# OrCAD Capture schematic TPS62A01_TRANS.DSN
size D; title: TPS62A01, 1-A High-Efficiency Synchronous; rev: 1.0; note: Datasheet: SLUSEG9B          EVM:SLUUCJ1; note: Synchronous Step Down Converter; note: Buck Converters in a SOT-563 Package
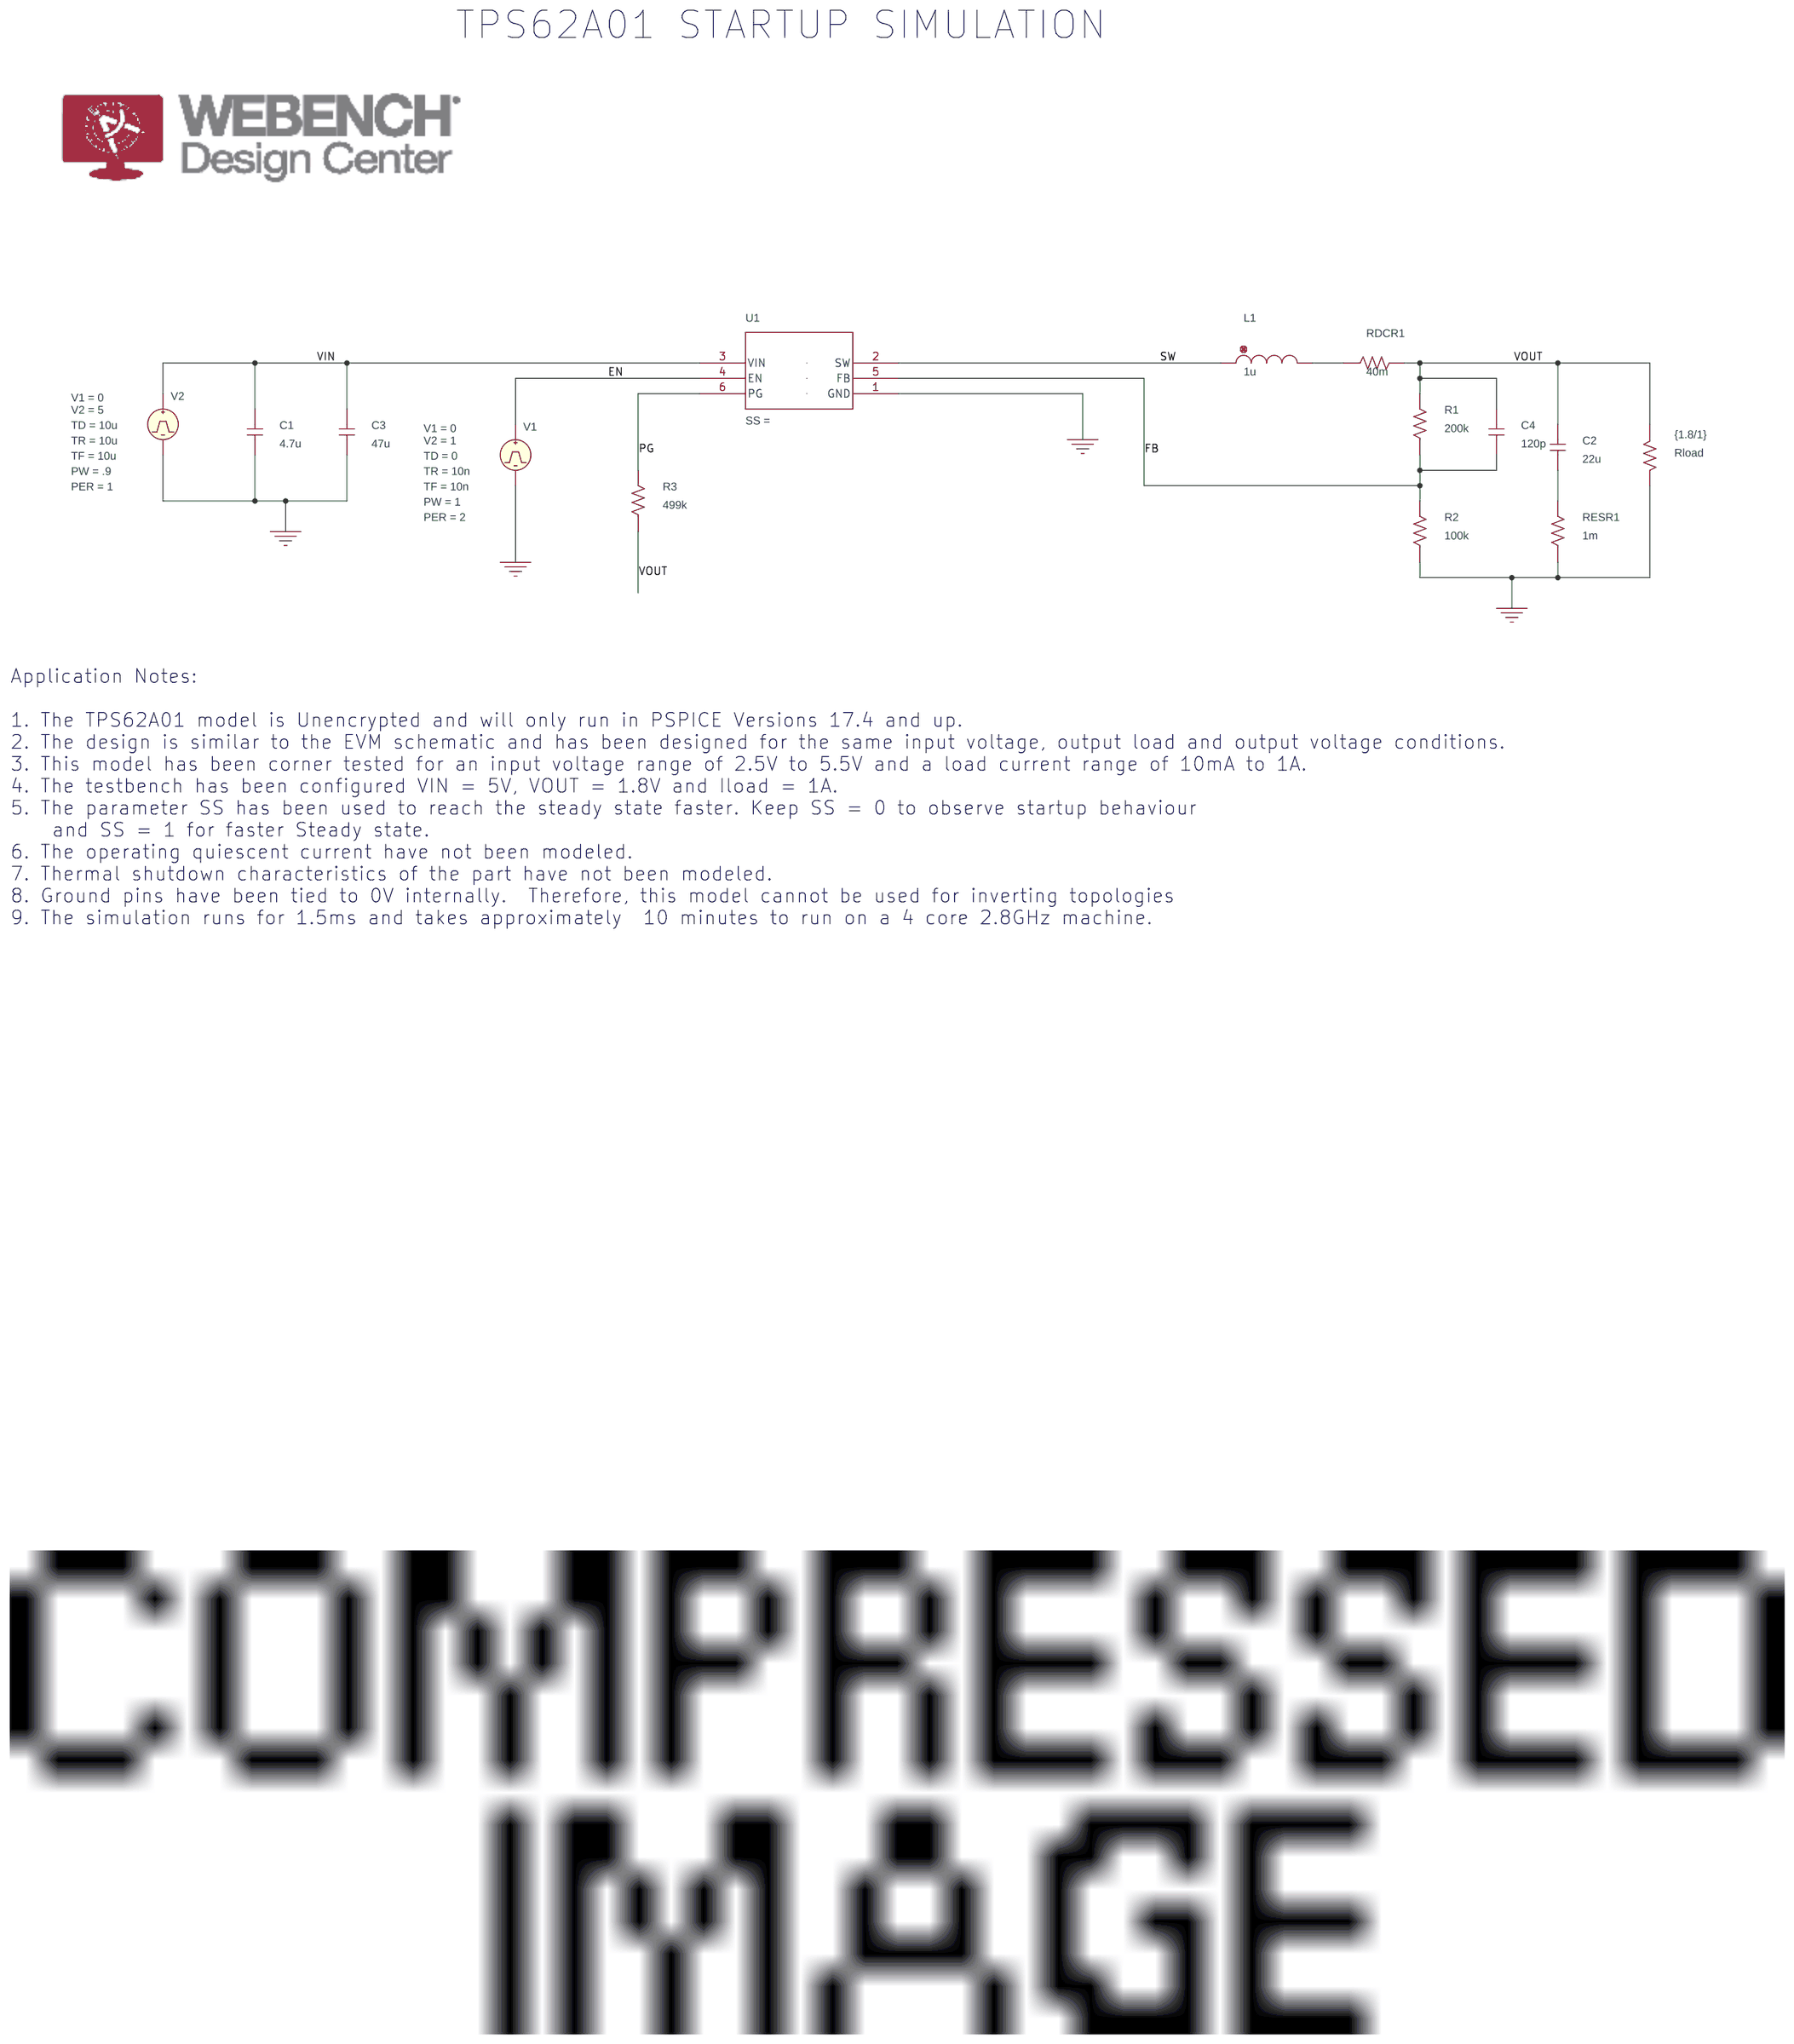
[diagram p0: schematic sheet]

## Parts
C1  4.7u  [RAD/CK05]
C2  22u  [RAD/CK05]
C3  47u  [RAD/CK05]
C4  120p  [RAD/CK05]
L1  1u  [DISC/.350x.175/LS.200x.100/.034]
R1  200k  [AX/RC05]
R2  100k  [AX/RC05]
R3  499k  [AX/RC05]
RDCR1  40m  [AX/RC05]
RESR1  1m  [AX/RC05]
Rload  {1.8/1}  [AX/RC05]
U1  Value  [DRL0006A-MFG]
V1  VPULSE
V2  VPULSE

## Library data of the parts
C1-C4 = C
L1 = L
R1-R3 RDCR1 RESR1 Rload = R
U1 = TPS62A01DRL_TRANS
V1 = VPULSE: PER: 2; PW: 1; TD: 0; TF: 10n; TR: 10n; V1: 0; V2: 1
V2 = VPULSE: PER: 1; PW: .9; TD: 10u; TF: 10u; TR: 10u; V1: 0; V2: 5

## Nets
VIN: C1.2 C3.2 U1.3(VIN) V2.1(+)
0: C1.1 C3.1 R2.1 RESR1.1 Rload.2 U1.1(GND) V1.2(-) V2.2(-)
EN: U1.4(EN) V1.1(+)
FB: C4.1 R1.1 R2.2 U1.5(FB)
PG: R3.2 U1.6(PG)
SW: L1.1 U1.2(SW)
VOUT: C2.2 C4.2 R1.2 R3.1 RDCR1.2 Rload.1
N16776436: L1.2 RDCR1.1
N16776762: C2.1 RESR1.2

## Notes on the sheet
- TPS62A01 STARTUP SIMULATION
- Application Notes:
  1. The TPS62A01 model is Unencrypted and will only run in PSPICE Versions 17.4 and up.
  2. The design is similar to the EVM schematic and has been designed for the same input voltage, output load and output voltage conditions.
  3. This model has been corner tested for an input voltage range of 2.5V to 5.5V and a load current range of 10mA to 1A.
  4. The testbench has been configured VIN = 5V, VOUT = 1.8V and Iload = 1A.
  5. The parameter SS has been used to reach the steady state faster. Keep SS = 0 to observe startup behaviour
      and SS = 1 for faster Steady state.
  6. The operating quiescent current have not been modeled.
  7. Thermal shutdown characteristics of the part have not been modeled.
  8. Ground pins have been tied to 0V internally.  Therefore, this model cannot be used for inverting topologies
  9. The simulation runs for 1.5ms and takes approximately  10 minutes to run on a 4 core 2.8GHz machine.
